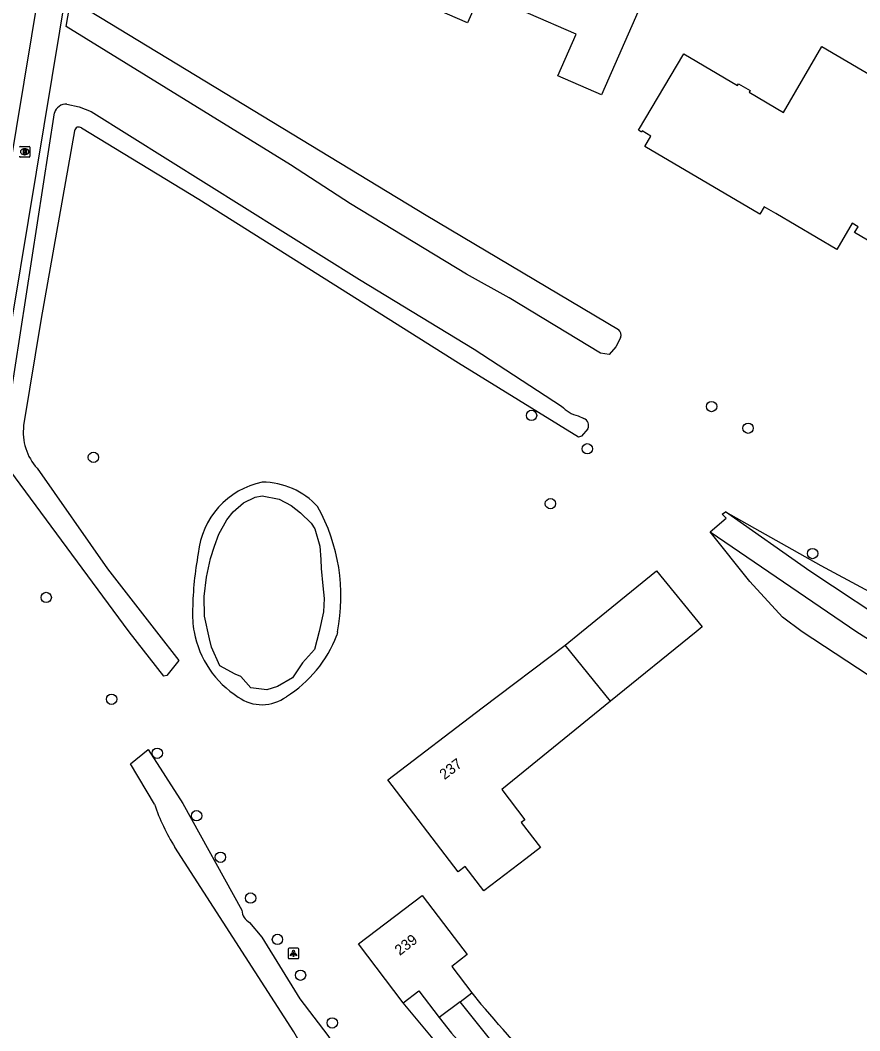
# Model space of a CAD drawing. Extents: x 161696 to 162377, y 380761 to 381673.
# Drawn here: x 161748.1 to 161827.5, y 380962.2 to 381057.9 of the extents above; entities that cross this region are included whole.
import ezdxf

# ---------------------------------------------------------------- set-up
doc = ezdxf.new("R2010")
doc.units = 0
for name, color, linetype in [('IMGEO_Boom', 7, 'Continuous'), ('IMGEO_Brandkraan', 7, 'Continuous'), ('IMGEO_Erf', 7, 'Continuous'), ('IMGEO_Fietspad_gesloten', 7, 'Continuous'), ('IMGEO_Groenvoorziening', 7, 'Continuous'), ('IMGEO_Lichtpunt', 7, 'Continuous'), ('IMGEO_Meer_plas_ven_vijver', 7, 'Continuous'), ('IMGEO_Pand', 7, 'Continuous'), ('IMGEO_Pand_nummerreeks', 7, 'Continuous'), ('IMGEO_Pand_vergunning_verleend', 7, 'Continuous'), ('IMGEO_Voetpad_open', 7, 'Continuous')]:
    doc.layers.add(name, color=color, linetype=linetype)

msp = doc.modelspace()

# ---------------------------------------------------------------- linework, layer by layer
at = {"layer": 'IMGEO_Boom'}
for centre in [(161813.515, 381021.332), (161796.47, 381020.495), (161816.962, 381019.276), (161801.75, 381017.328), (161754.988, 381016.521), (161798.253, 381012.137), (161823.075, 381007.418), (161750.521, 381003.261), (161756.71, 380993.622), (161761.037, 380988.514), (161764.758, 380982.602), (161767.01, 380978.665), (161769.872, 380974.806), (161772.416, 380970.895), (161774.602, 380967.503), (161777.606, 380962.985)]:
    msp.add_circle(centre, 0.489, dxfattribs=at)
at = {"layer": 'IMGEO_Brandkraan'}
for p, q in [((161748.06, 381045.946), (161748.912, 381045.946)), ((161748.986, 381045.872), (161748.986, 381045.02)), ((161748.912, 381044.946), (161748.06, 381044.946)), ((161748.496, 381045.166), (161748.471, 381045.166)), ((161748.473, 381045.726), (161748.498, 381045.726))]:
    msp.add_line(p, q, dxfattribs=at)
for points in [[(161748.06, 381045.946), (161748.912, 381045.946)], [(161748.986, 381045.872), (161748.986, 381045.02)], [(161748.912, 381044.946), (161748.06, 381044.946)], [(161748.333, 381045.646), (161748.333, 381045.246), (161748.546, 381045.246)], [(161748.564, 381045.646), (161748.333, 381045.646)], [(161748.512, 381045.565), (161748.458, 381045.565), (161748.458, 381045.489)], [(161748.458, 381045.489), (161748.511, 381045.489)], [(161748.52, 381045.413), (161748.458, 381045.413), (161748.458, 381045.332)], [(161748.458, 381045.332), (161748.52, 381045.332)]]:
    msp.add_lwpolyline(points, dxfattribs=at)
for centre, radius, start, end in [((161748.062, 381045.87), 0.0765, 91.55205, 178.44795), ((161748.062, 381045.87), 0.0765, 91.55205, 178.44795), ((161748.91, 381045.87), 0.0765, 1.55205, 88.44795), ((161748.91, 381045.87), 0.0765, 1.55205, 88.44795), ((161748.062, 381045.022), 0.0765, 181.55205, 268.44795), ((161748.062, 381045.022), 0.0765, 181.55205, 268.44795), ((161748.513, 381045.527), 0.0379, 267.82845, 90.93552), ((161748.521, 381045.372), 0.0404, 269.87594, 90.50774), ((161748.552, 381045.497), 0.251, 268.66757, 293.53466), ((161748.568, 381045.501), 0.145, 59.4692, 91.53667), ((161748.593, 381045.548), 0.0922, 285.51372, 58.15012), ((161748.598, 381045.356), 0.105, 301.31148, 78.98903), ((161748.91, 381045.022), 0.0765, 271.55205, 358.44795), ((161748.91, 381045.022), 0.0765, 271.55205, 358.44795)]:
    msp.add_arc(centre, radius, start, end, dxfattribs=at)
for centre, major_axis, ratio, start_param, end_param in [((161748.472, 381045.446), (-0.387, 0.002), 0.722429, 4.712389, 7.853982), ((161748.497, 381045.446), (-0.39, 0.002), 0.717154, 1.570796, 4.712389)]:
    msp.add_ellipse(centre, major_axis=major_axis, ratio=ratio, start_param=start_param, end_param=end_param, dxfattribs=at)
at = {"layer": 'IMGEO_Erf'}
msp.add_lwpolyline([(161778.103, 381000), (161778.037, 380999.676)], dxfattribs=at)
for centre, radius, start, end in [((161772.523, 381006.686), 7.646, 101.63161, 174.50088), ((161770.962, 381007.056), 7.119, 42.43972, 89.84873), ((161760.931, 381003.348), 17.495, 348.96756, 29.11312), ((161797.563, 381001.468), 33.189, 169.67085, 178.83486), ((161773.604, 381001.691), 9.235, 177.19241, 190.5493), ((161773.675, 381001.698), 9.305, 190.512, 237.71694), ((161766.889, 381003.982), 11.951, 302.19978, 338.88159), ((161770.955, 380996.964), 3.858, 234.31984, 306.63675)]:
    msp.add_arc(centre, radius, start, end, dxfattribs=at)
at = {"layer": 'IMGEO_Fietspad_gesloten'}
msp.add_lwpolyline([(161717.567, 380865.73), (161755.609, 381095.365)], dxfattribs=at)
at = {"layer": 'IMGEO_Groenvoorziening'}
for points in [[(161814.823, 381011.355), (161823.858, 381006.27), (161835.528, 381000), (161849.917, 380990.915), (161857.257, 380986.761), (161870.033, 380978.776)], [(161855.532, 380979.64), (161850.067, 380982.857), (161838.911, 380988.957), (161822.074, 381000), (161820.23, 381001.396), (161817.149, 381004.769), (161813.375, 381009.456)], [(161790.817, 380965.845), (161791.677, 380964.763)], [(161800.875, 380945.013), (161784.318, 380964.891)]]:
    msp.add_lwpolyline(points, dxfattribs=at)
msp.add_arc((161586.061, 380782.784), 274.58, 37.2662, 41.51008, dxfattribs=at)
at = {"layer": 'IMGEO_Lichtpunt'}
for p, q in [((161773.436, 380969.973), (161773.436, 380969.166)), ((161773.436, 380969.973), (161773.436, 380969.166)), ((161774.338, 380970.068), (161773.53, 380970.068)), ((161774.338, 380970.068), (161773.53, 380970.068)), ((161774.432, 380969.166), (161774.432, 380969.973)), ((161774.432, 380969.166), (161774.432, 380969.973)), ((161773.53, 380969.072), (161774.338, 380969.072)), ((161773.53, 380969.072), (161774.338, 380969.072))]:
    msp.add_line(p, q, dxfattribs=at)
for points in [[(161773.81, 380969.637), (161773.849, 380969.609), (161773.661, 380969.347), (161773.623, 380969.374), (161773.81, 380969.637)], [(161773.912, 380969.589), (161773.959, 380969.589), (161773.959, 380969.267), (161773.912, 380969.267), (161773.912, 380969.589)], [(161774.022, 380969.609), (161774.06, 380969.636), (161774.247, 380969.374), (161774.208, 380969.346), (161774.022, 380969.609)]]:
    msp.add_lwpolyline(points, dxfattribs=at)
msp.add_circle((161773.935, 380969.771), 0.0994, dxfattribs=at)
for centre, start, end in [((161773.53, 380969.973), 90, 180), ((161773.53, 380969.973), 90, 180), ((161774.338, 380969.973), 0, 90), ((161774.338, 380969.973), 0, 90), ((161773.53, 380969.166), 180, 270), ((161773.53, 380969.166), 180, 270), ((161774.338, 380969.166), 270, 0), ((161774.338, 380969.166), 270, 360)]:
    msp.add_arc(centre, 0.0946, start, end, dxfattribs=at)
at = {"layer": 'IMGEO_Meer_plas_ven_vijver'}
for points in [[(161752.401, 381057.311), (161752.841, 381059.901), (161786.5, 381039.453), (161804.694, 381028.617)], [(161804.89, 381027.847), (161804.453, 381026.983), (161803.808, 381026.26), (161802.991, 381026.386), (161794.338, 381031.604), (161790.304, 381033.846), (161779.332, 381040.531), (161773.659, 381044.196), (161752.401, 381057.311)], [(161752.481, 381049.952), (161753.657, 381049.697), (161754.776, 381049.254), (161780.175, 381033.345), (161791.03, 381026.773), (161799.319, 381021.373)], [(161746.478, 381017.885), (161751.295, 381049.116)], [(161753.2, 381047.427), (161750.033, 381029.675), (161748.386, 381019.526)], [(161801.809, 381019.225), (161801.206, 381018.521), (161800.909, 381018.431), (161789.553, 381025.434), (161764.963, 381040.916), (161753.875, 381047.693)], [(161800.89, 381020.46), (161801.424, 381020.189)], [(161756.315, 381005.977), (161760.971, 381000), (161763.091, 380997.278), (161761.926, 380995.875), (161761.642, 380995.803), (161758.374, 381000), (161747.065, 381015.314)], [(161749.669, 381015.485), (161756.315, 381005.977)], [(161766.086, 381006.958), (161766.444, 381008.109), (161766.874, 381009.24), (161767.621, 381010.591), (161768.231, 381011.35), (161769.198, 381012.204), (161770.288, 381012.76), (161770.951, 381012.892), (161772.587, 381012.573), (161773.698, 381011.95), (161774.597, 381011.269), (161775.604, 381010.285), (161775.963, 381009.752), (161776.427, 381008.107), (161776.512, 381006.856), (161776.557, 381006.003), (161776.725, 381004.358), (161776.823, 381003.151), (161776.771, 381001.911), (161776.375, 381000.049), (161775.918, 380998.342), (161774.771, 380997.069), (161773.849, 380995.648), (161772.421, 380994.824), (161771.416, 380994.509), (161769.889, 380994.691), (161768.961, 380995.771), (161768.396, 380995.989), (161766.944, 380996.783), (161766.165, 380998.568), (161765.967, 380999.329), (161765.511, 381001.473), (161765.47, 381003.357), (161765.704, 381005.164), (161766.086, 381006.958)], [(161813.375, 381009.456), (161814.901, 381010.754), (161814.611, 381011.057), (161814.519, 381011.152), (161814.823, 381011.355)], [(161878.838, 380970.995), (161849.981, 380988.26), (161837.224, 380996.217), (161831.506, 381000), (161822.827, 381005.742), (161814.823, 381011.355)], [(161813.375, 381009.456), (161827.27, 381000), (161837.063, 380993.83), (161850.304, 380985.897), (161866.936, 380975.124), (161872.076, 380972.049), (161880.821, 380966.339)], [(161760.771, 380983.701), (161758.488, 380987.51), (161760.185, 380988.854), (161763.461, 380983.765), (161769.031, 380973.648)], [(161769.779, 380972.48), (161770.921, 380971.109), (161774.526, 380965.283), (161777.183, 380961.798), (161782.274, 380954.09), (161782.196, 380953.716), (161780.817, 380952.755), (161780.068, 380952.859), (161775.096, 380960.155), (161773.976, 380962.159), (161762.713, 380979.614)], [(161810.2, 380939.746), (161801.127, 380950.717), (161789.707, 380964.999)], [(161787.723, 380963.487), (161788.886, 380962.034), (161800.609, 380948.972)]]:
    msp.add_lwpolyline(points, dxfattribs=at)
for centre, radius, start, end in [((161752.414, 381048.788), 1.166, 86.68715, 163.67214), ((161753.61, 381047.375), 0.414, 50.23374, 172.78249), ((161804.287, 381028.103), 0.655, 336.97112, 51.59107), ((161801.45, 381023.232), 2.828, 221.09831, 258.57493), ((161801.137, 381019.516), 0.732, 336.60372, 66.9376), ((161753.409, 381018.897), 5.062, 172.85905, 222.36979), ((161778.111, 380989.436), 18.264, 198.29958, 212.53129), ((161770.573, 380973.812), 1.551, 186.07735, 239.19454)]:
    msp.add_arc(centre, radius, start, end, dxfattribs=at)
at = {"layer": 'IMGEO_Pand'}
for points in [[(161829.887, 381036.116), (161827.056, 381037.804), (161827.381, 381038.349), (161826.835, 381038.674), (161825.363, 381036.206), (161819.611, 381039.592), (161818.504, 381040.242), (161818.084, 381039.53), (161807.195, 381045.94), (161807.775, 381046.926), (161806.952, 381047.41), (161806.89, 381047.306), (161806.607, 381047.473), (161810.876, 381054.726), (161815.977, 381051.722), (161816.072, 381051.885), (161817.152, 381051.249), (161817.056, 381051.085), (161820.313, 381049.166), (161823.955, 381055.411), (161830.134, 381051.769)], [(161799.641, 380998.745), (161801.185, 381000), (161808.311, 381005.79), (161812.619, 381000.488), (161812.038, 381000.016), (161803.949, 380993.443)], [(161803.949, 380993.443), (161793.648, 380985.07), (161795.829, 380982.207), (161795.5, 380981.956), (161797.311, 380979.58), (161795.916, 380978.517), (161791.939, 380975.486), (161790.175, 380977.802), (161789.512, 380977.297), (161782.875, 380986.006), (161791.796, 380992.805), (161799.641, 380998.745)], [(161803.949, 380993.443), (161799.641, 380998.745)], [(161784.318, 380964.891), (161780.075, 380970.459), (161786.115, 380975.061), (161789.145, 380971.085), (161790.385, 380969.458), (161788.917, 380968.339), (161790.817, 380965.845)], [(161784.318, 380964.891), (161785.796, 380966.017), (161787.723, 380963.487)], [(161789.707, 380964.999), (161790.817, 380965.845)], [(161789.707, 380964.999), (161787.723, 380963.487)]]:
    msp.add_lwpolyline(points, dxfattribs=at)
at = {"layer": 'IMGEO_Pand_vergunning_verleend'}
msp.add_lwpolyline([(161785.827, 381067.135), (161788.498, 381073.246), (161795.27, 381070.287), (161795.683, 381071.232), (161809.404, 381065.234), (161803.104, 381050.82), (161798.971, 381052.626), (161800.703, 381056.589), (161791.682, 381060.532), (161790.415, 381057.633), (161785.901, 381059.606), (161788.652, 381065.9), (161785.827, 381067.135)], dxfattribs=at)
at = {"layer": 'IMGEO_Voetpad_open'}
msp.add_lwpolyline([(161757.96, 381094.016), (161751.783, 381056.863), (161751.055, 381052.485), (161745.065, 381016.456), (161744.222, 381011.385), (161743.99, 381009.989), (161742.341, 381000), (161725.046, 380895.238), (161719.314, 380861.106), (161723.616, 380854.735)], dxfattribs=at)

# ---------------------------------------------------------------- texts
at = {"layer": 'IMGEO_Pand_nummerreeks'}
for s, rotation, p in [('237', 37.31227, (161788.227, 380985.962)), ('239', 37.30452, (161783.987, 380969.316))]:
    msp.add_text(s, height=1, rotation=rotation, dxfattribs=at).set_placement(p)

doc.saveas('drawing.dxf')
